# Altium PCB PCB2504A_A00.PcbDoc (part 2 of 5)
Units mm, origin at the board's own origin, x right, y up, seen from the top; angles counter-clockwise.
Board outline 115 x 60 mm, 6 copper layers (Top Layer, Signal Layer 2, Signal Layer 3, Signal Layer 4, Signal Layer 5, Bottom Layer), stack 1.555 mm thick; 403 components, 294 nets, 1344 pads, 774 vias.
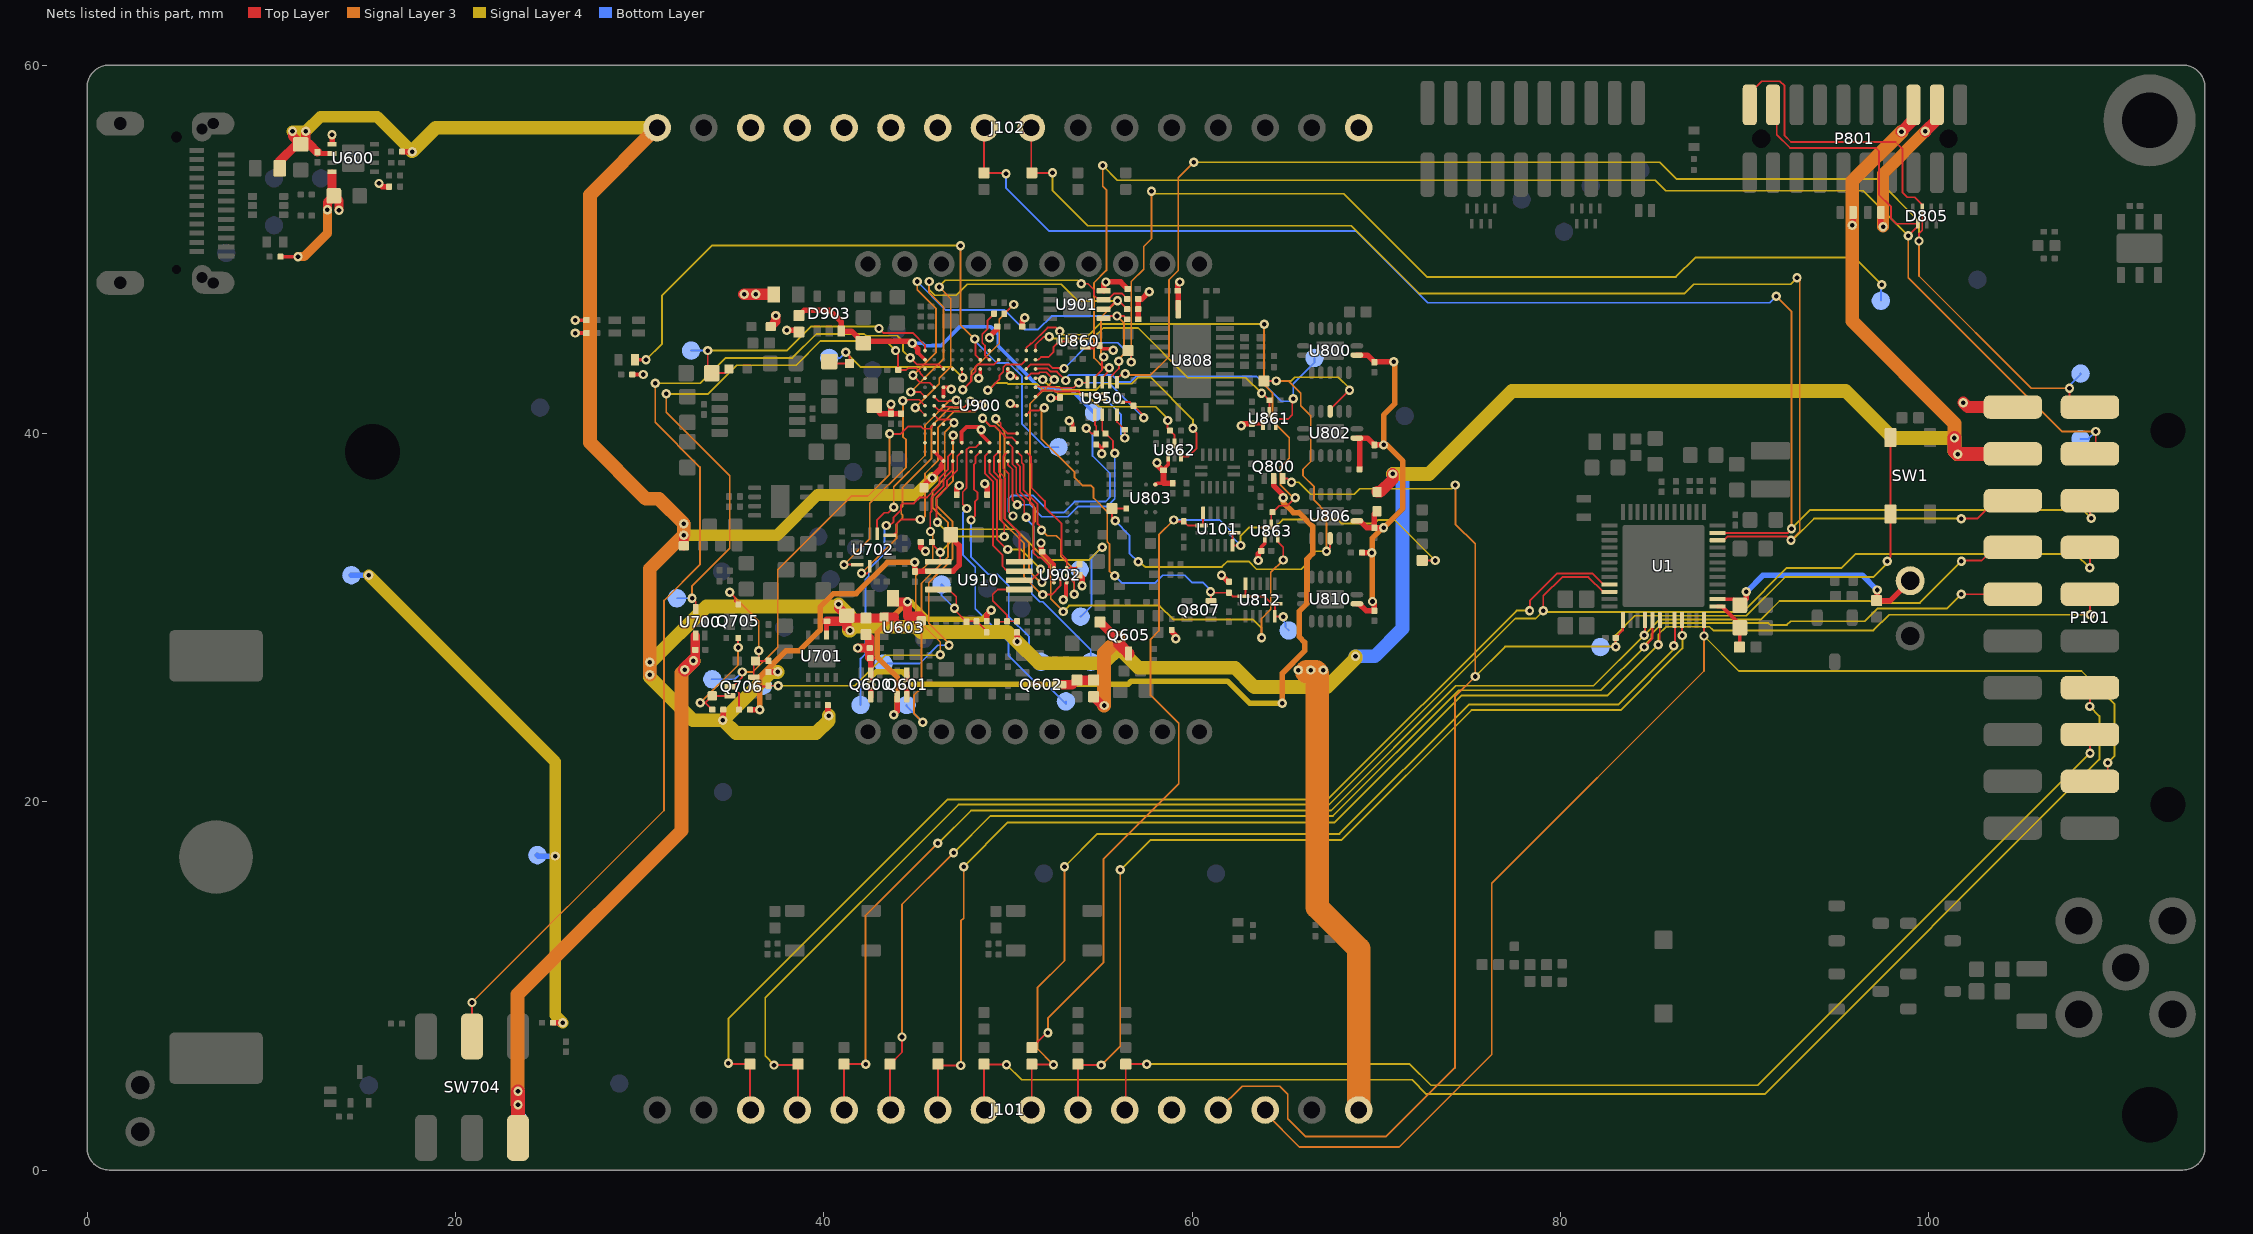
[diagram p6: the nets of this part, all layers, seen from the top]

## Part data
LED900: library part Yellow
LED901: library part Blue

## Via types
v1: diameter 0.508, hole 0.25, Top Layer to Bottom Layer, tented both sides, 774 vias

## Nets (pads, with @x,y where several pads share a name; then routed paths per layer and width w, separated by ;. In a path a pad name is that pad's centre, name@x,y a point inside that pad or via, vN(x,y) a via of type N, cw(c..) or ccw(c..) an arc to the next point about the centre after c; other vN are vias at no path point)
3V3: C607.1 C807.1 C808.1 C860.1 C862.1 C864.1 C866.1 C907.1 C908.1 C909.1 C910.1 C911.1 C914.1 C921.1 C922.1 C924.1 C925.1 C926.1 C927.1 C951.1 D807.1 J101.16 J102.16 L704.1 L900.1 P101.20 P801.3 R601.2 R756.2 R793.2 R838.2 R840.2 R903.1 R906.2 R907.1 R908.1 R909.1 R912.1 R919.1 R920.1 R928.2 R951.1 R952.1 R982.1 TPJ600.1 TPJ950.1 U600.1 U600.4 U803.A2 U808.1 U860.1 U861.1 U862.1 U863.1 U900.C6 U900.C9 U900.G3 U900.H11 U900.J11 U900.K3 U900.L4 U900.L7 U901.8 U902.A1 U902.E3 U910.2 | length 130.7
  Top Layer w0.2: R903.1@10.5,49.6 v1(11.45,49.6) ; U600.1@13.3,55.7 13.3,55.85 ; v1(26.5,45.45) R919.1@27.1,45.45 ; v1(26.5,46.15) R920.1@27.1,46.15 ; R912.1@29.6,43.2 v1(30.2,43.2) ; U900.H11@46.5,42 U900.J11@46.5,42.5 46.825,42.5 v1(46.925,42.4) ; U900.C9@47.5,39.5 47.482,39.518 47.482,40.083 47.749,40.35 48.425,40.35 48.55,40.225 v1@48.55,40.075 ; v1(48.425,43) 48.45,43 48.5,43.05 U900.L7@48.5,43.5 ; v1(48.55,40.2) v1@48.55,40.075 ; U900.C6@49,39.5 48.525,39.975 48.55,40 v1@48.55,40.075 ; U900.L4@50,43.5 50,43.35 50.15,43.2 50.15,43.15 v1(50.125,43.125) 50.375,43.125 U900.K3@50.5,43 ; v1(50.125,41.625) 50.25,41.5 U900.G3@50.5,41.5 ; C914.1@51.875,33.575 51.875,33.525 52.5,32.9 U902.A1@52.5,32.7 ; v1(52.325,41.925) 52.325,41.9 52.4,41.825 52.5,41.925 C911.1@52.825,41.925 ; v1(53,30.975) 53.157,31.132 53.157,31.857 U902.E3@53.2,31.9 ; v1(53.336,40.692) 53.336,40.714 53.325,40.725 53.35,40.725 53.525,40.55 C909.1@53.525,40.225 ; U860.1@54.2,44.65 54.625,44.65 54.75,44.775 C862.1@54.975,44.775 55.157,44.593 55.657,44.593 v1(55.725,44.525) ; R951.1@54.8,39.4 54.9,39.4 55.1,39.2 ; v1(55.1,38.9) 55.1,39.2 ; R952.1@55.3,39.4 55.1,39.2 ; U803.A2@58,37.225 58.032,37.257 58.083,37.257 58.126,37.3 58.475,37.3 ; C860.1@58.45,38 58.45,38.05 58.7,38.3 U862.1@58.7,38.75 ; C864.1@63.25,40.525 63.775,40.525 U861.1@63.85,40.45 ; C866.1@63.75,33.625 63.75,33.825 63.95,34.025 U863.1@63.95,34.35
  Top Layer w0.25: 13.3,54.05 U600.4@13.3,54.2
  Top Layer w0.3: 13.3,55.85 v1(13.3,56.225) ; v1(15.85,53.575) 16.025,53.4 R601.2@16.4,53.4 ; R793.2@25.3,8 v1(25.825,8) ; R756.2@36,25 v1(36.525,25) ; v1(38,45.6) 38.55,45.6 R928.2@38.65,45.5 ; C907.1@42.75,41.4 43.075,41.075 C924.1@43.65,41.075 ; v1(43.65,41.575) C924.1@43.65,41.075 ; C925.1@44.2,41.075 C924.1@43.65,41.075 ; v1(44.95,33) C922.1@44.95,32.5 44.975,32.525 U910.2@46.225,32.525 47.025,32.525 47.35,32.85 47.35,33.925 C921.1@46.825,34.45 ; R982.1@45.275,34.1 45.275,33.8 45.45,33.625 45.5,33.625 v1(45.525,33.6) ; C927.1@47.225,36.675 47.225,37.05 v1(47.35,37.175) ; v1(48.75,37.275) 48.75,37.225 48.875,37.1 C926.1@48.875,36.675 ; v1(49.002,45.202) 48.998,45.202 48.925,45.275 49,45.275 49.425,45.701 C910.1@49.425,45.8 ; C908.1@50.775,45.8 50.775,46.1 50.925,46.25 v1(50.925,46.275) ; v1(51.8,34.05) 51.8,33.65 C914.1@51.875,33.575 ; R906.2@53.899,32.298 54.025,32.172 v1@54.025,31.729 ; v1@54.025,31.725 v1@54.025,31.729 ; v1(54.028,31.727) v1@54.025,31.729 ; U901.8@55.2,47.75 55.2,48.1 v1(55.325,48.225) 56.125,48.225 C951.1@56.5,47.85 ; R908.1@57.075,46.2 R907.1@57.075,46.75 R909.1@57.075,47.3 57.275,47.3 v1(57.675,47.7) ; v1(58.1,38.4) 58.05,38.4 58.025,38.425 58,38.4 58.4,38 C860.1@58.45,38 58.45,37.325 58.475,37.3 C807.1@58.95,37.3 ; R838.2@58.9,29.325 58.9,29.225 59.15,28.975 59.15,28.85 v1(59.125,28.85) ; U808.1@59.25,46.745 59.25,47.725 C808.1@59.225,47.75 59.225,48.125 v1(59.325,48.225) ; v1(61.6,32.3) 61.95,31.95 R840.2@62,31.95 ; v1(62.675,40.425) 62.775,40.525 C864.1@63.25,40.525 ; v1(63.6,33.1) 63.6,33.475 C866.1@63.75,33.625 ; D807.1@97.4,52 97.4,51.35 v1(97.525,51.225)
  Top Layer w0.5: v1(13.05,52.15) 13.05,52.55 C607.1@13.4,52.9 ; 13.3,54.05 13.3,53 C607.1@13.4,52.9 ; v1(13.675,52.125) 13.675,52.625 C607.1@13.4,52.9 ; L704.1@37.125,45.8 37.4,46.075 v1(37.4,46.4)
  Top Layer w0.635: v1(35.675,47.55) v1(36.3,47.55) L900.1@37.285,47.55 ; v1(99.825,56.4) 100.445,57.02 P801.3@100.445,57.841 ; v1(101.875,41.675) 102.12,41.43 P101.20@104.57,41.43
  Signal Layer 3 w0.3: v1(36.525,25) 36.525,26.772 37.964,28.211 38.686,28.211 39.8,29.325 39.8,30.574 40.526,31.3 41.753,31.3 43.453,33 v1(44.95,33) ; v1@48.998,45.202 v1(49.002,45.202)
  Signal Layer 3 w0.5: v1(11.45,49.6) 11.775,49.6 13.05,50.875 v1(13.05,52.15)
  Signal Layer 3 w0.635: v1(97.525,51.225) 97.525,54.1 v1(99.825,56.4)
  Signal Layer 3 w1.27: v1@66.227,27.05 66.725,27.05 66.8,26.975 66.8,14.275 69.05,12.025 J101.16@69.05,3.262
  Signal Layer 4 w0.635: v1(15.3,32.3) 25.425,22.175 v1(25.425,17.05) 25.425,8.4 v1(25.825,8)
  Bottom Layer w0.3: TPJ600.1@14.353,32.302 v1(15.3,32.3) ; TPJ950.1@24.452,17.1 24.502,17.05 v1(25.425,17.05)
  other v1: 65.775,27.15 66.45,27.15 67.125,27.15
3V6_SW: C608.1 L702.1 Q601.1 R639.2 U603.B1 | length 17.3
  Top Layer w0.2: U603.B1@44.55,29.65 44.55,30.075
  Top Layer w0.3: v1@43.8,24.8 v1(43.8,24.725) 44,24.925 Q601.1@44,25.7 ; R639.2@48.85,29.8 48.85,30.15 v1(49.1,30.4) v1@49,30.4
  Top Layer w0.5: L702.1@43.765,31.05 43.965,30.85 v1(44.55,30.85) 44.55,30.075 45.225,30.075 C608.1@45.3,30
  Signal Layer 3 w0.3: v1(43.8,24.725) 44,24.925 44,26.75 42.9,27.85 42.9,29.2 v1(44.55,30.85)
  Signal Layer 4 w0.3: v1(44.55,30.85) 44.75,30.85 45.7,29.9 48.6,29.9 v1(49.1,30.4)
3V6_SW_SENSE: C641.1 R639.1 R640.2 TP923.1 U910.4 | length 6.3
  Top Layer w0.1: U910.4@46.225,31.525 46.795,31.525 47.2,31.12 47.2,30.6 v1(47.1,30.5) ; v1@47.1,30.6 v1(47.1,30.5) ; R639.1@48.85,29.2 48.85,29.25 R640.2@48.3,29.8 47.775,29.8 C641.1@47.75,29.775 47.1,30.425 v1(47.1,30.5)
  Bottom Layer w0.1: TP923.1@46.675,31.525 TP923.1@46.4,31.8 46.4,31.2 v1(47.1,30.5)
5V: C600.1 C609.1 C611.1 C702.1 C703.1 C901.1 D806.1 J102.1 L600.2 L700.1 L800.1 P101.18 P801.5 Q605.3 R600.2 R622.2 R633.2 R680.1 R690.2 R700.2 R714.2 R755.2 U600.2 U603.A2 U603.B2 U701.2 U900.A11 U900.B12 | length 233.2
  Top Layer w0.2: C702.1@40.15,29.775 C702.1@40.175,29.8 ; 43.85,30.025 44.15,29.725 U603.B2@44.15,29.65 44.025,29.65 43.9,29.525 43.9,29.375 44.025,29.25 U603.A2@44.15,29.25 ; U900.B12@46,39 U900.A11@46.5,38.5 46.375,38.375 46.375,38.25
  Top Layer w0.25: C600.1@12.5,55.275 12.575,55.2 U600.2@13.3,55.2 ; U701.2@40.15,29.05 C702.1@40.15,29.775
  Top Layer w0.3: R600.2@17.1,55.3 v1(17.65,55.3) ; v1(34.525,24.425) 34.55,24.425 R714.2@34.55,25 ; R755.2@37,27.05 v1(37.5,27.05) ; R700.2@40.225,25.25 40.225,24.725 v1(40.275,24.675) ; C901.1@45.45,37.05 45.45,37.184 v1@45.902,37.637 ; v1(45.902,37.577) v1@45.902,37.637 ; v1@45.908,37.642 v1@45.902,37.637 ; v1@45.913,37.647 46.375,38.109 46.375,38.25 ; v1(50.5,28.7) R633.2@50.5,29.2 ; v1(95.85,51.3) 95.9,51.35 D806.1@95.9,52
  Top Layer w0.5: L600.2@10.465,54.4 10.465,54.79 11.375,55.7 C611.1@11.6,55.7 ; v1(11.15,56.4) 11.15,56.15 C611.1@11.6,55.7 ; v1(11.875,56.4) 11.875,55.975 C611.1@11.6,55.7 ; C600.1@12.5,55.275 12.075,55.7 C611.1@11.6,55.7 ; L700.1@32.4,33.9 v1(32.4,34.475) ; C702.1@40.175,29.8 40.95,29.8 C703.1@41.25,30.1 ; v1(40.8,30.725) 40.8,30.55 C703.1@41.25,30.1 ; v1(41.425,29.3) 41.25,29.475 C703.1@41.25,30.1 ; 43.85,30.025 C609.1@43.275,30.025 43.225,29.975 R622.2@42.3,29.975 41.375,29.975 C703.1@41.25,30.1 ; R680.1@54.65,25.7 55.125,25.225 v1(55.225,25.225) ; R690.2@55,29.75 55.011,29.75 55.886,28.875 v1(56.025,28.875)
  Top Layer w0.635: v1(56.025,28.875) 56.025,28.575 Q605.3@56.55,28.05 ; L800.1@70.05,36.825 70.225,36.825 70.9,37.5 v1(70.9,37.8) ; v1(98.525,56.375) 99.175,57.025 P801.5@99.175,57.841
  Top Layer w0.75: v1(101.4,39.75) 101.4,39.05 v1(101.575,38.875) 101.59,38.89 P101.18@104.57,38.89
  Signal Layer 3 w0.75: v1(30.55,26.9) v1(30.55,27.575) 30.55,32.65 32.4,34.5 v1(32.4,35.1) 31.05,36.45 30.35,36.45 27.3,39.5 27.3,52.952 J102.1@30.95,56.602 ; v1(55.225,25.225) 55.225,28.075 v1(56.025,28.875) ; v1(98.525,56.375) 95.85,53.7 v1(95.85,51.3) 95.85,46.1 101.4,40.55 v1(101.4,39.75) 101.4,39.05 v1(101.575,38.875)
  Signal Layer 4 w0.635: v1(11.15,56.4) v1(11.875,56.4) 12.675,57.2 15.75,57.2 v1(17.65,55.3) ; v1(32.4,34.475) 37.475,34.475 39.66,36.66 44.986,36.66 v1(45.902,37.577)
  Signal Layer 4 w0.75: v1@17.65,55.318 18.934,56.602 J102.1@30.95,56.602 ; v1(32.4,34.475) v1(32.4,35.1) ; v1(37.5,27.05) 37.15,27.05 v1(34.525,24.425) ; v1(40.275,24.675) 40.275,24.41 39.59,23.725 35.225,23.725 v1(34.525,24.425) ; v1@40.8,30.708 40.692,30.6 33.625,30.6 30.6,27.575 v1(30.55,27.575) v1(30.55,26.9) 30.55,26.775 32.9,24.425 v1(34.525,24.425) ; v1(40.8,30.725) 41.425,30.1 v1(41.425,29.3) ; v1@41.364,29.3 v1(41.425,29.3) ; v1(56.025,28.875) 56.025,28.35 ; v1(68.875,27.9) 68.875,27.775 67.325,26.225 63.375,26.225 62.325,27.275 57.1,27.275 56.025,28.35 ; v1(70.9,37.8) 72.875,37.8 72.975,37.9 77.375,42.3 95.5,42.3 98.05,39.75 v1(101.4,39.75) 101.4,39.05 v1(101.575,38.875) ; v1(41.425,29.3) 41.625,29.5 45,29.5 45.282,29.218 49.982,29.218 v1(50.5,28.7) 51.675,27.525 55.2,27.525 56.025,28.35
  Bottom Layer w0.75: v1(68.875,27.9) 69.925,27.9 71.425,29.4 71.425,37.375 71,37.8 v1(70.9,37.8)
5V_BUF: Q602.3 R680.2 R681.2 | length 2
  Top Layer w0.5: Q602.3@52.8,26.35 53.5,26.35 R681.2@53.75,26.6 R680.2@54.65,26.6
5V_DH_SW: C803.1 C805.1 C809.1 C827.1 L800.2 R807.1 R808.1 U800.14 U802.14 U806.14 U810.14 | length 24.8
  Top Layer w0.3: U810.14@68.95,30.75 69.075,30.75 69.45,30.375 C827.1@69.9,30.375 69.9,30.775 v1(69.8,30.875) ; U806.14@68.95,35.25 69.125,35.25 69.5,34.875 C809.1@69.9,34.875 ; U802.14@68.95,39.75 U802.14@69.1,39.75 ; U800.14@68.95,44.25 69.525,44.25 C803.1@69.9,43.875 69.925,43.9 v1(70.95,43.9) ; R807.1@69.1,38.05 U802.14@69.1,39.75 ; R808.1@69.225,33.525 v1(69.75,33.525) ; L800.2@70.05,35.775 69.9,35.625 C809.1@69.9,34.875 ; v1(70.4,34.875) C809.1@69.9,34.875 ; v1(70.4,39.375) C805.1@69.9,39.375 69.525,39.75 U802.14@69.1,39.75
  Signal Layer 3 w0.3: v1(69.8,30.875) 69.8,30.975 69.775,31 69.775,34.3 70.35,34.875 v1(70.4,34.875) 71.45,35.925 71.45,38.5 70.575,39.375 v1(70.4,39.375) 70.4,41 71,41.6 71,43.85 v1(70.95,43.9)
5V_SENSE: C635.1 R633.1 R634.2 U910.7 | length 4.4
  Top Layer w0.1: C635.1@49.4,29.775 49.925,29.775 R634.2@49.95,29.8 ; R633.1@50.5,29.8 R634.2@49.95,29.8 ; U910.7@50.625,31.525 49.444,31.525 49.182,31.263 49.182,30.918 49.95,30.15 R634.2@49.95,29.8
5V_SW: C610.1 Q600.2 Q600.5 Q601.2 Q601.5 Q800.5 R622.1 R623.2 | length 43.6
  Top Layer w0.3: C610.1@42.525,27.8 42.55,27.775 Q600.5@42.55,27 42.55,26.375 v1(42.55,26.35) Q600.2@42.55,25.7 ; Q601.2@44.5,25.7 v1(44.5,26.375) Q601.5@44.5,27 ; Q800.5@64.425,37.55 64.425,37.175 64.95,36.65 v1(64.95,36.5)
  Top Layer w0.5: v1(41.85,28.35) R623.2@42.5,28.35 ; R622.1@42.3,29.075 42.5,28.875 R623.2@42.5,28.35 ; C610.1@42.525,27.8 42.5,27.825 R623.2@42.5,28.35
  Signal Layer 3 w0.3: v1(64.9,25.35) 64.9,26.975 66.118,28.193 66.118,28.654 65.825,28.947 65.825,30.35 66.243,30.768 66.243,33.168 66.55,33.475 66.55,34.95 65.8,35.7 65.5,35.7 64.95,36.25 v1(64.95,36.5)
  Signal Layer 4 w0.3: v1(42.55,26.35) 42.55,26.751 42.849,27.05 44.275,27.05 44.5,26.825 v1(44.5,26.375) 56.525,26.375 56.7,26.55 61.925,26.55 63.125,25.35 v1(64.9,25.35)
#RESET: R805.2 R809.1 R810.2 U802.4 U806.11 | length 34
  Top Layer w0.1: v1(55.825,35.25) 55.65,35.425 R810.2@55.65,35.925 R809.1@56.425,35.925 ; R805.2@63.9,42.85 v1(64.575,42.85) ; v1(67.3,33.6) 67.5,33.8 U806.11@67.5,34.3 ; U802.4@67.5,41.2 67.5,41.325 68.525,42.35 v1(68.55,42.35)
  Signal Layer 3 w0.1: v1(64.575,42.85) 65.225,42.85 65.9,42.175 65.9,41.506 66.45,40.956 66.45,38.475 66.025,38.05 66.025,37.7 66.625,37.1 66.625,36.375 67.3,35.7 v1(67.3,33.6)
  Signal Layer 4 w0.1: v1(57.075,33.025) 57.175,33.025 57.432,32.768 57.438,32.768 57.456,32.75 61.625,32.75 61.925,33.05 63.075,33.05 63.5,32.625 65.925,32.625 66.357,33.057 66.357,33.257 66.7,33.6 v1(67.3,33.6) ; v1(64.575,42.85) 65.381,42.85 65.581,43.05 67.95,43.05 68.55,42.45 v1(68.55,42.35)
  Bottom Layer w0.1: v1(55.825,35.25) 56.6,34.475 56.6,33.5 v1(57.075,33.025)
ADC0: C130.1 R129.2 U1.25 | length 2.9
  Top Layer w0.2: U1.25@88.535,30.6 88.775,30.6 89.75,29.625 C130.1@89.75,29.45 89.75,28.425 R129.2@89.725,28.4
ADC1: J101.14 P101.3 U1.24 | length 72.6
  Top Layer w0.1: v1(87.8,29) U1.24@87.8,29.865 ; P101.3@108.76,21.11 109.385,21.11 109.725,21.45 v1(109.725,22.125)
  Signal Layer 3 w0.1: J101.14@63.97,3.262 63.97,3.105 65.825,1.25 71.25,1.25 76.275,6.275 76.275,15.575 87.8,27.1 v1(87.8,29)
  Signal Layer 4 w0.1: v1(87.8,29) 89.7,27.1 108.3,27.1 110.1,25.3 110.1,22.5 v1(109.725,22.125)
ADC_VREF: C117.1 R116.1 TPH101.1 U1.26 | length 12.9
  Top Layer w0.2: U1.26@88.535,31 89.425,31 C117.1@89.75,30.675
  Top Layer w0.3: C117.1@89.75,30.675 90.1,31.025 v1(90.1,31.4) ; v1(97.2,31.5) 97.2,30.95 R116.1@97.175,30.925 97.925,30.925 TPH101.1@99,32
  Bottom Layer w0.3: v1(90.1,31.4) 91,32.3 96.4,32.3 v1(97.2,31.5)
ADC_VREF_ENABLE: R112.1 R118.2 R306.2 U101.5 U101.6 U101.12 U101.13 | length 54.5
  Top Layer w0.1: R306.2@51.3,6.65 52.1,7.45 v1(52.175,7.45) ; v1(59,35.3) 59.075,35.225 R112.1@59.55,35.225 59.775,35 U101.13@60.515,35 60.6,35.085 U101.12@60.6,35.685 U101.12@60.6,35.95 ; U101.6@62.285,34.6 62.2,34.515 U101.5@62.2,33.915 v1(62.64,33.915) ; R118.2@72.5,33.1 v1(73.2,33.1)
  Signal Layer 3 w0.1: v1(52.175,7.45) 52.175,8.25 55.2,11.275 55.2,16.9 59.275,20.975 59.275,24.25 57.75,25.775 57.75,28.825 58.2,29.275 58.2,34.5 v1(59,35.3)
  Signal Layer 4 w0.1: v1(62.64,33.915) 62.64,34.44 63.1,34.9 64.5,34.9 64.918,35.318 67.918,35.318 68.136,35.1 69.9,35.1 70.1,35.3 71,35.3 v1(73.2,33.1)
  Bottom Layer w0.1: v1(59,35.3) 61.5,35.3 62.07,34.73 62.07,34.485 v1(62.64,33.915)
AEM_5V_#ENABLE: U900.L10
AEM_BYPASS_#EN: C709.1 Q705.2 Q706.6 R714.1 | length 6.6
  Top Layer w0.1: v1(33.3,25.375) 33.575,25.375 ; R714.1@33.95,25 33.575,25.375 ; Q706.6@34.9,25.75 C709.1@33.95,25.75 33.575,25.375 ; v1(35.35,28.375) Q705.2@35.35,28.888
  Signal Layer 3 w0.1: v1(33.3,25.375) 35.35,27.425 v1(35.35,28.375)
AEM_BYPASS_ENABLE: Q706.2 R754.2 TP720.1 U900.F12 | length 27.4
  Top Layer w0.1: Q706.2@36.2,26.25 36.95,26.25 R754.2@37,26.3 v1(37.525,26.3) ; U900.F12@46,41 46.25,40.75 46.9,40.75 v1(47.075,40.575)
  Signal Layer 3 w0.1: v1@46.325,27.95 v1(46.325,27.975) 46.325,28.675 45.3,29.7 45.3,31.85 46.75,33.3 46.75,35.15 46.568,35.332 46.568,35.338 46.338,35.568 46.332,35.568 45.9,36 45.9,36.9 46.575,37.575 46.575,40.075 v1(47.075,40.575)
  Signal Layer 4 w0.1: v1(37.525,26.3) 41.675,26.3 43.332,27.957 46.307,27.957 v1(46.325,27.975)
  Bottom Layer w0.1: TP720.1@36.7,26.3 v1(37.525,26.3)
AEM_CALIBRATE0: U702.13 U900.G11 | length 14.9
  Top Layer w0.1: v1(42.05,32.4) 41.95,32.4 42.35,32.4 42.5,32.55 U702.13@42.5,32.79 ; U900.G11@46.5,41.5 46.55,41.45 46.999,41.45 47.04,41.409 47.609,41.409 v1(47.952,41.752) 47.975,41.775 v1@48,41.775
  Signal Layer 3 w0.1: v1(42.05,32.4) 43.425,33.775 43.957,34.307 43.957,35.088 44.275,35.406 44.275,35.55 44.275,35.569 44.207,35.637 44.207,35.963 44.275,36.031 44.275,37.05 45.85,38.625 45.85,40.4 46.85,41.4 47.6,41.4 v1(47.952,41.752)
AEM_CALIBRATE1: U702.5 U900.G12 | length 13.4
  Top Layer w0.1: U702.5@43.585,34.475 43.775,34.475 43.957,34.657 43.957,35.088 44.194,35.325 v1(45.25,35.325) ; U900.G12@46,41.5 46.25,41.25 46.604,41.25 46.652,41.202 48.227,41.202 v1(48.575,41.55)
  Signal Layer 3 w0.1: v1(45.25,35.325) 45.35,35.325 45.5,35.475 45.5,37.825 46.2,38.525 46.2,40.3 47.093,41.193 48.218,41.193 v1(48.575,41.55)
AEM_CALIBRATE2: U702.6 U900.H12 | length 10.7
  Top Layer w0.1: U702.6@42.9,34.56 42.9,35.306 43.287,35.693 43.493,35.693 v1(43.8,36) ; U900.H12@46,42 46.25,41.75 47.15,41.75 v1(47.202,41.802)
  Signal Layer 3 w0.1: v1(43.8,36) 43.8,37.1 45.5,38.8 45.5,40.45 46.852,41.802 v1(47.202,41.802)
AEM_CALIBRATE3: U702.12 U900.G13 | length 12.6
  Top Layer w0.1: v1(41.1,32.875) U702.12@41.815,32.875 ; v1(44.3,41.775) 44.3,41.657 44.332,41.625 44.532,41.825 45.175,41.825 U900.G13@45.5,41.5
  Signal Layer 3 w0.1: v1(41.1,32.875) 42.5,34.275 42.5,36.2 44.475,38.175 44.475,39.656 44.3,39.831 v1(44.3,41.775)
AEM_CURRENT_HIGH_GAIN: C720.1 R764.2 TP706.1 U900.N13 | length 16.3
  Top Layer w0.1: v1(33.7,44.5) 33.7,43.5 R764.2@33.925,43.275 34.625,43.275 C720.1@34.85,43.5 ; v1(43,45.7) 43.25,45.45 44.85,45.45 45.5,44.8 U900.N13@45.5,44.5
  Signal Layer 4 w0.1: v1(33.7,44.5) 38,44.5 39.3,45.8 42.9,45.8 v1(43,45.7)
  Bottom Layer w0.1: TP706.1@32.8,44.5 v1(33.7,44.5)
AEM_CURRENT_LOW_GAIN: C724.1 R768.2 TP707.1 U900.L9 | length 10.3
  Top Layer w0.1: R768.2@40.3,43.9 40.4,43.8 C724.1@41.4,43.8 41.4,44.2 v1(41.2,44.4) ; U900.L9@47.5,43.5 47.5,43.2 47.575,43.125 v1@47.552,43.102 ; v1(47.55,43.025) v1@47.55,43.1 ; v1@47.55,43.1 47.525,43.1 47.527,43.102 v1@47.552,43.102 ; v1@47.55,43.1 v1@47.552,43.102
  Signal Layer 4 w0.1: v1(41.2,44.4) 42,43.6 46.975,43.6 v1(47.55,43.025)
  Bottom Layer w0.1: TP707.1@40.3,44.1 40.9,44.1 v1(41.2,44.4)
AEM_SENSE_#EN: C747.1 Q705.5 Q706.3 R755.1 | length 6.9
  Top Layer w0.1: v1(34.902,31.377) 35.169,31.109 35.169,30.894 Q705.5@35.35,30.713 ; Q706.3@36.2,26.75 36.2,27.55 C747.1@36.3,27.65 ; v1(36.475,28.2) 36.475,27.825 C747.1@36.3,27.65 ; R755.1@37,27.65 C747.1@36.3,27.65
  Signal Layer 3 w0.1: v1(34.902,31.377) 36.475,29.803 v1(36.475,28.2)
AEM_SENSE_ENABLE: Q706.5 R756.1 TP721.1 U900.E12 | length 24.3
  Top Layer w0.1: Q706.5@34.9,26.25 Q706.5@35.05,26.25 ; R756.1@35.4,25 35.4,25.9 Q706.5@35.05,26.25 ; v1(35.567,27.046) 35.567,26.767 Q706.5@35.05,26.25 ; v1(43.575,39.975) 44.179,39.975 44.586,40.382 45.264,40.382 45.396,40.25 45.75,40.25 U900.E12@46,40.5
  Signal Layer 3 w0.1: v1(35.567,27.046) 36.146,27.046 37.5,28.4 37.5,32.6 41.5,36.6 42.4,36.6 43.575,37.775 v1(43.575,39.975)
  Bottom Layer w0.1: TP721.1@33.9,26.65 TP721.1@33.95,26.65 35.171,26.65 v1(35.567,27.046)
AEM_SENSE_SELECT: U900.L13
AEM_SWITCH_POS: SW704.2 U900.L11 | length 59.4
  Top Layer w0.1: SW704.2@20.9,7.25 v1(20.9,9.1) ; v1(44.7,44.1) 45.05,43.75 46.25,43.75 U900.L11@46.5,43.5
  Signal Layer 3 w0.1: v1(20.9,9.1) 31.325,19.525 31.325,30.925 33.275,32.875 33.275,38.175 30.85,40.6 v1(30.85,42.725)
  Signal Layer 4 w0.1: v1(30.85,42.725) 33.3,42.725 34.675,44.1 38.3,44.1 39.6,45.4 42.2,45.4 42.3,45.3 43.5,45.3 44,45.3 44.3,45 44.3,44.5 v1(44.7,44.1)
AEM_VMCU: C708.1 SW704.4 TP709.1 U700.1 | length 34.2
  Top Layer w0.5: v1(32.925,27.65) 33.025,27.75 C708.1@33.025,28.25 U700.1@33.025,29
  Top Layer w0.75: SW704.4@23.4,1.75 v1(23.4,3.55) v1(23.4,4.275) ; v1(32.45,27.175) v1(32.925,27.65)
  Signal Layer 3 w0.75: v1(23.4,3.55) 23.375,3.575 23.375,9.525 32.275,18.425 32.275,27 v1(32.925,27.65)
  Bottom Layer w0.635: v1(23.4,4.275) v1(23.4,3.55) 23.425,3.525 TP709.1@23.425,2.725
AEM_VMCU_ENABLE: R763.2 TP715.1 U700.4 U900.K13 | length 31.6
  Top Layer w0.1: v1(32.85,31.05) 33.05,30.85 U700.4@33.05,30.475 ; v1(43.9,44.5) 44.025,44.375 44.025,43.475 R763.2@44.05,43.45 44.485,43.45 44.578,43.543 45.013,43.543 45.243,43.313 45.243,43.257 U900.K13@45.5,43
  Signal Layer 3 w0.1: v1(31.45,42.15) 31.45,41.15 34.9,37.7 34.9,33.775 32.85,31.725 v1(32.85,31.05)
  Signal Layer 4 w0.1: v1(31.45,42.15) 33.725,42.15 35.275,43.7 38.5,43.7 39.825,45.025 43.375,45.025 v1(43.9,44.5)
  Bottom Layer w0.1: TP715.1@32.025,31.05 v1(32.85,31.05)
BC_ADC_SPI_CIPO: U900.B6 U910.9 | length 9.2
  Top Layer w0.1: U900.B6@49,39 48.75,38.75 48.75,37.831 49.2,37.381 49.2,33.9 ; 49.2,35.4 49.2,33.9 ; U910.9@50.625,32.525 49.975,32.525 49.7,32.8 49.7,33.4 49.2,33.9
BC_ADC_SPI_COPI: U900.A6 U910.8 | length 9
  Top Layer w0.1: U900.A6@49,38.5 49,37.863 49.4,37.463 49.4,35 49.4,34.7 49.4,34.244 49.944,33.7 v1(50,33.7) v1@50,33.65 ; U910.8@50.625,32.025 51.275,32.025 51.775,32.525 v1(51.775,32.625)
  Signal Layer 4 w0.1: v1(50,33.7) 50.7,33.7 v1(51.775,32.625)
BC_ADC_SPI_CS: R982.2 U900.B5 U910.1 | length 10.7
  Top Layer w0.1: R982.2@45.875,34.1 45.875,34 v1(46.325,33.55) 46.325,33.125 U910.1@46.225,33.025 ; U900.B5@49.5,39 49.25,38.75 49.25,37.896 49.65,37.496 49.65,35.25 ; 49.65,35.811 49.65,35.25 ; v1@49.8,34.275 v1(49.8,34.4) 49.8,35.1 49.65,35.25
  Signal Layer 4 w0.1: v1(46.325,33.55) 47.175,34.4 v1(49.8,34.4)
BC_ADC_SPI_SCLK: U900.A5 U910.10 | length 5.9
  Top Layer w0.1: U900.A5@49.5,38.5 49.5,37.929 49.85,37.579 49.85,35.375 50.625,34.6 U910.10@50.625,33.025
BC_ADC_VREF: C919.1 D903.3 R928.1 TPJ905.1 U900.M13 | length 21.3
  Top Layer w0.2: 45.1,44.4 U900.M13@45.5,44
  Top Layer w0.3: R928.1@38.65,46.4 38.95,46.7 40.325,46.7 40.95,46.075 D903.3@40.95,45.55 41.5,45.55 C919.1@42.15,44.9 42.25,45 44.4,45 44.7,45 v1(44.8,44.9) 45.1,44.6 45.1,44.4
  Bottom Layer w0.2: v1(44.8,44.9) 45.374,44.9 45.517,44.757 45.883,44.757 45.901,44.775 46.375,44.775 47.4,45.8 49.05,45.8 49.475,45.375 49.475,44.75 51.2,43.025 51.2,42.999 51.774,42.425 53.379,42.425 TPJ905.1@54.678,41.126
BC_BUTTON_ENABLE: R981.1 U900.H1 U950.6 U950.12 | length 8.2
  Top Layer w0.1: U900.H1@51.5,42 51.832,42.332 52.474,42.332 52.526,42.28 53.845,42.28 54.025,42.1 U950.6@54.24,42.1 55.075,42.1 v1(55.175,42) ; U950.12@55.925,41.015 55.925,40.625 R981.1@56.35,40.2 v1(56.35,39.75)
  Bottom Layer w0.1: v1@55.1,42.075 v1(55.175,42) 56.138,41.037 56.138,39.962 v1(56.35,39.75)
BC_DAC_OUT: U900.N6
BC_DBG_#RESET: LED903.1 TPJ956.1 U900.M7 | length 37
  Top Layer w0.1: v1(48.2,45.125) 48.25,45.075 48.25,44.25 U900.M7@48.5,44
  Top Layer w0.2: LED903.1@29.75,44 v1(30.35,44)
  Signal Layer 3 w0.1: v1(47.425,50.2) 47.425,45.9 v1(48.2,45.125)
  Signal Layer 4 w0.1: v1(30.35,44) 31.225,44.875 31.225,47.5 33.925,50.2 v1(47.425,50.2)
  Bottom Layer w0.1: v1(48.2,45.125) 48.2,45.025 49.4,43.825 50.046,43.825 50.775,43.096 50.775,40.5 52.024,39.251 TPJ956.1@52.753,39.251
BC_DBG_TCK_SWCLK: TPJ954.1 U900.C10 | length 18.5
  Top Layer w0.1: U900.C10@47,39.5 47,39.775 46.95,39.825 46.95,39.85 47,39.9 v1(47.025,39.9) ; v1@47.125,39.852 v1@47.125,39.9
  Signal Layer 3 w0.1: 46.25,32.45 45.7,31.9 ; v1(46.8,28.5) 46.8,28.6 45.7,29.7 45.7,31.9 ; v1(47.025,39.9) 47.025,37.425 46.132,36.532 46.132,36.068 47,35.2 47,33.2 45.7,31.9
  Bottom Layer w0.1: TPJ954.1@43.253,27.501 45.201,27.501 46.2,28.5 v1(46.8,28.5) ; v1@46.957,39.832 v1(47.025,39.9)
BC_DBG_TDO_SWO: TPJ955.1 U900.A10 | length 17
  Top Layer w0.1: v1@45.85,34.725 v1(45.8,34.675) 45.782,34.693 45.782,35.699 45.85,35.767 45.85,36.484 46.495,37.129 46.495,37.522 47,38.027 U900.A10@47,38.5
  Signal Layer 3 w0.1: v1(45.375,24.325) 44.9,24.8 44.9,25.775 45.318,26.193 45.318,29.282 45,29.6 45,32.264 45.918,33.182 45.918,34.557 v1(45.8,34.675)
  Bottom Layer w0.1: TPJ955.1@44.503,25.251 44.503,25.197 v1(45.375,24.325)
BC_DBG_TMS_SWDIO: TPJ953.1 U900.B10 | length 16.8
  Top Layer w0.1: v1(43.4,35) 43.587,35 43.793,35.207 43.793,35.438 44.193,35.837 44.193,36.093 44.3,36.2 44.9,36.2 45.225,36.525 45.608,36.525 46.295,37.212 46.295,37.605 46.75,38.06 46.75,38.75 U900.B10@47,39
  Bottom Layer w0.1: TPJ953.1@42.001,25.251 42.001,27.776 42.275,28.05 42.275,32.069 42.443,32.237 42.443,32.618 43.3,33.475 43.3,35.15 43.4,35.05 v1(43.4,35)
BC_DISP_COM: U900.E11
BC_DISP_PWR_ENABLE: U900.D12
BC_DISP_SPI_COPI: U900.B8
BC_DISP_SPI_CS: U900.C12
BC_DISP_SPI_SCLK: U900.C13
BC_I2C_EXP_ENABLE: R950.1 U900.J1 U950.5 U950.13 | length 9.1
  Top Layer w0.1: U900.J1@51.5,42.5 51.5,42.532 52.556,42.532 52.608,42.48 53.58,42.48 v1(53.85,42.75) 54.29,42.75 U950.5@54.325,42.785 ; U950.13@56.01,41.7 56.625,41.7 R950.1@56.825,41.5 57.375,40.95 v1(57.375,40.85)
  Bottom Layer w0.1: v1(53.85,42.75) 55.475,42.75 v1(57.375,40.85)
BC_I2C_EXP_SCL: D805.5 P101.17 P801.17 TPJ651.1 U950.3 | length 90.4
  Top Layer w0.1: U950.3@55.125,42.785 55.125,43.025 55.275,43.175 ; 55.275,43.175 55.375,43.275 55.4,43.3 55.4,43.475 v1(55.5,43.575) ; P801.17@91.555,57.841 91.75,57.647 91.75,56.225 92.475,55.5 97.15,55.5 97.3,55.35 97.3,52.975 97.95,52.325 97.95,51.675 98.24,51.385 D805.5@99.4,51.385 99.4,51.25 v1(98.892,50.742) ; P101.17@108.76,38.89 108.76,39.135 109.075,39.45 109.075,40 109.025,40.05 109.077,40.102 v1(109.08,40.102)
  Signal Layer 3 w0.1: v1(55.15,54.55) 55.15,53.431 55.35,53.231 55.35,48.85 54.675,48.175 54.675,44.1 55.2,43.575 v1(55.5,43.575) ; v1(98.892,50.742) 98.892,48.458 107.248,40.102 v1(109.08,40.102)
  Signal Layer 4 w0.1: v1(55.15,54.55) 55.95,53.75 85.15,53.75 85.725,53.175 96.459,53.175 v1(98.892,50.742)
  Bottom Layer w0.1: TPJ651.1@108.25,39.7 108.678,39.7 v1(109.08,40.102)
BC_I2C_EXP_SDA: D805.3 P101.19 P801.19 TPJ650.1 U950.1 | length 90.1
  Top Layer w0.1: U950.1@55.925,42.785 55.925,42.975 56.2,43.25 v1(56.375,43.25) ; P801.19@90.285,57.841 90.285,58.485 90.925,59.125 91.925,59.125 92.175,58.875 92.175,56.175 92.525,55.825 98.2,55.825 98.575,55.45 98.575,53.1 98.85,52.825 99.25,52.825 99.65,52.425 D805.3@99.65,52.215 99.65,51.025 99.475,50.85 v1(99.475,50.45) ; v1(107.65,42.45) 107.65,41.8 108.02,41.43 P101.19@108.76,41.43
  Signal Layer 3 w0.1: v1(56.375,43.25) 56.45,43.175 57.75,43.175 58.75,44.175 58.75,48.348 59.25,48.848 59.25,53.875 v1(60.1,54.725) ; v1(99.475,50.45) 99.475,48.55 105.575,42.45 v1(107.65,42.45)
  Signal Layer 4 w0.1: v1(60.1,54.725) 85.4,54.725 86.3,53.825 97.175,53.825 99.475,51.525 v1(99.475,50.45)
  Bottom Layer w0.1: v1(107.65,42.45) 107.65,42.625 108.25,43.225 TPJ650.1@108.25,43.248
BC_SPI_CIPO: U900.B3 U902.C3 | length 10.5
  Top Layer w0.1: U900.B3@50.5,39 50.75,38.75 50.75,38.396 50.85,38.296 50.85,36.921 51.61,36.16 51.61,35.09 51.825,34.875 v1(51.825,34.75) ; U902.C3@53.2,32.3 53.6,31.9 v1(53.6,31.275)
  Signal Layer 3 w0.1: v1(51.825,34.75) 52.132,34.443 52.638,34.443 52.868,34.213 52.868,33.332 53.6,32.6 v1(53.6,31.275)
BC_SPI_COPI: U900.C3 U902.D2 | length 15
  Top Layer w0.1: v1(48.625,40.825) 49.043,40.407 49.284,40.407 49.916,39.775 50.225,39.775 U900.C3@50.5,39.5 ; v1(51.9,31.25) 52.375,31.25 52.85,31.725 U902.D2@52.85,32.1
  Signal Layer 3 w0.1: v1(48.625,40.825) 49.05,40.4 49.282,40.4 49.565,40.117 49.565,35.335 50.875,34.025 50.875,32.225 51.85,31.25 v1(51.9,31.25)
BC_SPI_CS: R906.1 U900.B2 U902.A3 | length 8
  Top Layer w0.1: U900.B2@51,39 51.25,38.75 51.25,38.396 51.3,38.346 51.3,37.037 52.01,36.326 52.01,35.995 52.92,35.086 52.92,33.424 53.2,33.144 U902.A3@53.2,32.7 53.701,32.7 R906.1@53.899,32.898
BC_SPI_SCLK: U900.A3 U902.E1 | length 7.5
  Top Layer w0.1: U900.A3@50.5,38.5 50.5,38.364 50.65,38.214 50.65,36.838 51.4,36.088 51.4,33.5 51.635,33.265 51.781,33.265 52.238,32.809 52.238,32.162 U902.E1@52.5,31.9
BC_TRACECLK: TPJ957.1 U900.B7 | length 13.6
  Top Layer w0.1: v1(48,35.3) 48.207,35.507 48.207,36.301 48.343,36.437 48.343,36.794 48.157,36.979 48.157,38.304 48.25,38.396 48.25,38.75 U900.B7@48.5,39
  Bottom Layer w0.1: v1(48,35.3) 48,33.275 48.925,32.35 49.425,32.35 50.05,31.725 50.05,30.05 51.15,28.95 51.15,28.248 TPJ957.1@51.799,27.599
BC_TRACED0: TPJ958.1 U900.C7 | length 17.7
  Top Layer w0.1: v1(47.775,35.925) 47.55,36.15 47.55,36.819 47.75,37.019 47.75,38.55 47.75,39.104 47.896,39.25 48.25,39.25 U900.C7@48.5,39.5
  Bottom Layer w0.1: v1(47.775,35.925) 47.568,35.718 47.568,33.382 48.225,32.725 48.225,30.475 50.025,28.675 50.025,27.95 51.575,26.4 52.059,26.4 53.15,25.309 TPJ958.1@53.15,25.45
BC_TRACED1: TPJ959.1 U900.C4 | length 14
  Top Layer w0.1: U900.C4@50,39.5 50.25,39.25 50.25,38.331 50.45,38.131 50.45,36.755 50.893,36.312 50.893,35.532 v1@50.975,35.45 ; v1@51,35.425 v1@50.975,35.45 ; v1(51,35.45) v1@50.975,35.45
  Bottom Layer w0.1: v1(51,35.45) 51,35.375 51.407,34.968 51.407,33.718 51.3,33.611 51.3,31.294 51.737,30.857 51.893,30.857 54.499,28.251 TPJ959.1@54.499,27.599
BC_TRACED2: TPJ960.1 U900.D3 | length 13.9
  Top Layer w0.1: v1(49.35,40.8) 49.61,40.54 49.61,40.364 49.974,40 U900.D3@50.5,40
  Signal Layer 3 w0.1: v1(49.35,40.8) 49.35,40.615 49.765,40.2 49.765,40.16 49.825,40.1 49.825,35.375 51.137,34.062 51.137,32.538 51.75,31.925 v1(51.85,31.925)
  Bottom Layer w0.1: v1(51.85,31.925) 52.523,32.598 TPJ960.1@53.899,32.598
BC_TRACED3: TPJ961.1 U900.B9 | length 18.8
  Top Layer w0.1: v1(46.175,35.175) 46.132,35.218 46.132,36.484 46.695,37.047 46.695,37.44 47.25,37.994 47.25,38.75 U900.B9@47.5,39
  Signal Layer 4 w0.1: v1(46.175,35.175) 46.55,34.8 50.425,34.8 52.1,33.125 54.4,33.125 55.1,33.825 v1(55.125,33.825)
  Bottom Layer w0.1: TPJ961.1@53.95,30.05 54.549,30.649 54.549,33.249 54.7,33.4 v1(55.125,33.825)
BC_UIF_BUTTON0: R951.2 U900.B4 U950.9 | length 17.2
  Top Layer w0.1: U900.B4@50,39 49.75,38.75 49.75,38.1 50.05,37.8 50.05,35.74 v1(50.275,35.515) ; v1(54.25,40.275) 54.525,40 R951.2@54.8,40 54.8,40.4 54.725,40.475 U950.9@54.725,41.015
  Bottom Layer w0.1: v1(50.275,35.515) 50.025,35.765 50.025,36.45 50.2,36.625 51.375,36.625 52.3,35.7 53.025,35.7 53.625,36.3 55.3,36.3 55.55,36.55 55.55,37.825 54.6,38.775 54.6,39.925 v1(54.25,40.275) v1@54.194,40.275
BC_UIF_BUTTON1: R952.2 U900.A4 U950.10 | length 13.4
  Top Layer w0.1: U900.A4@50,38.5 50,38.298 50.25,38.048 50.25,36.375 v1(50.5,36.125) ; U950.10@55.125,41.015 55.125,40.175 R952.2@55.3,40 55.71,39.59 55.71,39.015 v1(55.8,38.925)
  Bottom Layer w0.1: v1(50.5,36.125) 51.2,36.125 51.85,35.475 53.25,35.475 53.8,36.025 55.375,36.025 55.8,36.45 v1(55.8,38.925)
BC_VCOM_CTS: U863.3 U900.K2 | length 34
  Top Layer w0.1: U900.K2@51,43 51.25,43.25 51.669,43.25 51.737,43.318 52.086,43.318 52.525,42.879 v1(52.525,42.925) ; v1@52.5,42.825 52.55,42.775 v1@52.575,42.8 ; U863.3@64.65,34.35 64.65,34.125 64.95,33.825 v1(64.95,33.125)
  Signal Layer 3 w0.1: v1(52.525,42.925) 51.2,41.6 51.2,36.2 51.475,35.925 51.475,35.225 51.375,35.125 51.375,33.825 52.325,32.875 52.325,31.025 52.975,30.375 v1@52.975,30.3 ; v1@52.975,30.275 v1@52.975,30.3 ; v1@53.001,30.326 v1@52.975,30.3 ; v1(63.775,28.9) 63.775,29.95 64.275,30.45 64.275,32.45 v1(64.95,33.125)
  Signal Layer 4 w0.1: v1(53.003,30.326) 53.326,30.65 58.225,30.65 58.975,29.9 63.306,29.9 63.775,29.431 v1(63.775,28.9)
BC_VCOM_CTS_DIR: R853.2 U863.5 U900.N2 | length 27
  Top Layer w0.1: U900.N2@51,44.5 51,44.642 51.233,44.875 51.283,44.875 52.158,45.75 52.625,45.75 v1(52.825,45.55) ; U863.5@64.3,35.05 64.3,35.65 R853.2@64.375,35.725 64.725,36.075 65.175,36.075 v1(65.6,36.5)
  Signal Layer 3 w0.1: v1(63.925,45.925) 63.9,45.9 63.9,42.667 64.375,42.192 64.375,40.669 65.275,39.769 65.275,38.656 64.982,38.363 64.982,38.357 64.8,38.175 64.8,37.206 v1@65.6,36.406 ; v1(65.6,36.5) v1@65.6,36.406 ; v1@65.65,36.356 v1@65.6,36.406
  Signal Layer 4 w0.1: v1(52.825,45.55) 53.018,45.357 54.407,45.357 55,45.95 v1@63.925,45.95
BC_VCOM_ENABLE: Q807.3 R840.1 TP930.1 U812.5 U812.6 U812.12 U812.13 U900.F2 | length 25.5
  Top Layer w0.1: U900.F2@51,41 51.25,41.25 51.7,41.25 51.85,41.4 v1(51.975,41.4) ; v1(61,31.4) v1@61.025,31.375 ; Q807.3@61.15,30.9 Q807.3@61.025,30.9 v1@61.025,31.375 ; U812.12@62.9,31.835 62.9,31.235 U812.13@62.815,31.15 ; U812.6@64.585,30.75 U812.6@64.5,30.75 ; v1(64.95,30.05) 64.935,30.065 U812.5@64.5,30.065 U812.6@64.5,30.75 ; v1@61.025,31.375 61.05,31.35 R840.1@62,31.35 62.2,31.15 U812.13@62.815,31.15 ; U812.13@62.815,31.15 63.925,31.15 64.325,30.75 U812.6@64.5,30.75
  Signal Layer 3 w0.1: v1(51.975,41.4) 51.832,41.257 51.832,39.693 53.625,37.9 53.625,37.6 54.05,37.175 54.5,37.175 54.657,37.018 54.657,36.493 55.4,35.75 55.4,34.106 55.518,33.988 55.518,32.507 55.775,32.25 55.8,32.25 55.803,32.253 v1(55.803,32.277)
  Bottom Layer w0.1: v1(55.803,32.277) 56.204,31.875 57.975,31.875 58.4,32.3 59.6,32.3 60,31.9 60.6,31.9 61,31.5 v1(61,31.4) ; v1(64.95,30.05) 64.95,29.825 65.075,29.7 65.075,29.475 TP930.1@65.25,29.3
BC_VCOM_RTS: U862.3 U900.K1 | length 12.7
  Top Layer w0.1: U900.K1@51.5,43 51.825,43 v1(51.9,42.925) ; U862.3@59.4,38.75 59.8,38.75 60.25,39.2 60.25,40 60.05,40.2 v1(60.05,40.275)
  Signal Layer 4 w0.1: v1(51.9,42.925) 52.3,42.525 52.799,42.525 52.974,42.35 54.775,42.35 55.125,42.7 56.725,42.7 57.068,43.043 57.757,43.043 60.05,40.75 v1(60.05,40.275)
BC_VCOM_RTS_DIR: R852.2 U862.5 U900.M2 | length 15.3
  Top Layer w0.1: v1(48.9,42.35) 48.956,42.35 49.54,42.935 49.54,43.14 49.75,43.35 49.75,43.604 49.896,43.75 50.75,43.75 U900.M2@51,44 ; v1(58.675,40.7) 58.675,40.275 R852.2@58.8,40.15 59.05,39.9 U862.5@59.05,39.45
  Signal Layer 4 w0.1: v1(48.9,42.35) 48.956,42.35 49.349,42.743 49.943,42.743 50.011,42.675 51.594,42.675 51.944,42.325 52.55,42.325 52.725,42.15 54.225,42.15 54.925,41.45 58.031,41.45 58.675,40.806 v1(58.675,40.7)
BC_VCOM_RXD: R882.2 TPJ606.1 U900.L2 | length 61
  Top Layer w0.1: U900.L2@51,43.5 51.25,43.75 52.219,43.75 52.412,43.557 53.018,43.557 v1(53.05,43.525) ; R882.2@56.525,44.5 56.7,44.325 v1(56.7,43.875)
  Signal Layer 3 w0.1: v1(56.7,43.875) 56.7,48.25 57.375,48.925 57.375,50.15 57.8,50.575 v1(57.8,53.15)
  Signal Layer 4 w0.1: v1(57.8,53.15) 57.932,53.018 68.232,53.018 72.75,48.5 86.275,48.5 87.325,49.55 95.982,49.55 v1(97.455,48.077)
  Bottom Layer w0.1: v1(53.05,43.525) 54.45,44.925 55.975,44.925 56.7,44.2 v1(56.7,43.875) ; TPJ606.1@97.404,47.202 v1@97.404,47.996
BC_VCOM_RXD_DIR: R850.2 U860.5 U900.M1 | length 2.6
  Top Layer w0.1: U900.M1@51.5,44 51.65,44 51.8,44.15 52.219,44.15 52.275,44.206 52.275,44.219 52.468,44.412 52.468,44.668 R850.2@52.8,45 U860.5@53.5,45
BC_VCOM_TXD: TPJ607.1 U861.3 U900.L1 | length 20.2
  Top Layer w0.1: U900.L1@51.5,43.5 51.518,43.518 52.169,43.518 52.329,43.357 52.662,43.357 53.144,42.875 v1(53.15,42.875) ; U861.3@64.55,40.45 64.55,40.575 64.758,40.782 65.213,40.782 65.443,41.012 65.443,41.818 v1(65.5,41.875)
  Bottom Layer w0.1: v1(53.15,42.875) 53.15,43 53.325,43.175 55.65,43.175 56.025,42.8 56.675,42.8 56.975,43.1 63.5,43.1 64.85,41.75 65.375,41.75 v1(65.5,41.875) 65.5,42.7 66.653,43.853 TPJ607.1@66.653,44.101
BC_VCOM_TXD_DIR: R851.2 U861.5 U900.N1 | length 15.8
  Top Layer w0.1: U900.N1@51.5,44.5 51.5,44.809 51.941,45.25 v1(52.25,45.25) ; v1(63.775,42.175) 63.825,42.175 R851.2@64.2,41.8 U861.5@64.2,41.15
  Signal Layer 4 w0.1: v1(52.25,45.25) 52.25,45.189 52.218,45.157 54.607,45.157 55.175,45.725 57.075,45.725 59.775,43.025 62.925,43.025 v1(63.775,42.175)
BOARD_ID_SCL: R907.2 U900.H13 U901.6 U950.4 | length 26.1
  Top Layer w0.1: v1(44.725,42.25) 45.25,42.25 U900.H13@45.5,42 ; U950.4@54.725,42.785 54.725,43.05 55.107,43.432 55.107,44.107 55.15,44.15 v1(55.2,44.15) ; U901.6@55.2,46.75 55.42,46.75 55.87,47.2 v1(55.95,47.2) 56.025,47.2 R907.2@56.475,46.75
  Signal Layer 3 w0.1: v1(44.725,42.25) 45.975,43.5 46.5,44.025 46.5,46.875 45.975,47.4 45.725,47.65 v1(45.725,48.25) ; v1(55.2,44.15) 55.15,44.15 55.057,44.243 55.057,46.307 v1(55.95,47.2)
  Signal Layer 4 w0.1: v1(45.725,48.25) 45.725,47.8 46.025,47.5 47.2,47.5 47.8,48.1 52.9,48.1 53.8,47.2 v1(55.95,47.2)
BOARD_ID_SDA: R908.2 U900.J12 U901.5 U950.2 | length 25.4
  Top Layer w0.1: v1(44.85,43.15) 45.25,42.75 45.75,42.75 U900.J12@46,42.5 ; U901.5@55.2,46.25 55.5,46.25 55.5,46.3 55.575,46.375 v1(55.925,46.375) 56.3,46.375 R908.2@56.475,46.2 ; U950.2@55.525,42.785 55.525,43.025 56.025,43.525 v1(56.025,43.925) ; v1@55.925,46.35 55.925,46.25 v1@55.975,46.2
  Signal Layer 3 w0.1: v1(44.85,43.15) 45.7,44 46.1,44.4 46.1,46.775 45.7,47.175 45.075,47.8 v1(45.075,48.25) ; v1(55.925,46.375) 56.3,46 56.3,44.3 56.025,44.025 v1(56.025,43.925)
  Bottom Layer w0.1: v1(45.075,48.25) 46.625,46.7 49.825,46.7 50.857,45.668 50.874,45.668 50.891,45.65 51.65,45.65 52.375,46.375 v1(55.925,46.375)
BOARD_ID_WP: R909.2 U900.F13 U901.7 | length 19.6
  Top Layer w0.1: v1(44.975,41.4) 45.1,41.4 U900.F13@45.5,41 ; v1(53.975,48.125) 54.35,48.125 54.675,47.8 54.675,47.5 54.925,47.25 U901.7@55.2,47.25 55.42,47.25 55.77,47.6 56.175,47.6 R909.2@56.475,47.3
  Signal Layer 3 w0.1: v1(44.975,41.4) 46.275,42.7 46.275,43 46.9,43.625 46.9,47.325 v1(46.275,47.95) v1@46.275,48
  Signal Layer 4 w0.1: v1@46.275,48 46.593,48.318 53.782,48.318 v1(53.975,48.125)
BOARD_VER0: R930.1 U900.M5 | length 9.5
  Top Layer w0.1: v1(47.55,42.375) 48,42.825 48,43.125 48.032,43.157 48.032,43.163 48.25,43.381 48.25,43.604 48.25,43.65 48.35,43.75 49.25,43.75 U900.M5@49.5,44 ; R930.1@49.8,46.5 50.3,47 v1(50.325,47)
  Signal Layer 3 w0.1: v1(47.55,42.375) 48.025,42.85 48.025,43.375 49.532,44.882 49.532,46.207 v1(50.325,47)
BOARD_VER1: R931.1 U900.M6 | length 2.9
  Top Layer w0.1: U900.M6@49,44 48.75,44.25 48.75,44.775 48.61,44.916 48.61,45.384 48.9,45.675 48.9,46.15 R931.1@49.25,46.5
BREAKOUT_BOT3: J101.3 R314.1 U1.9 | length 64.6
  Top Layer w0.1: v1(34.825,5.8) 34.875,5.75 R314.1@36,5.75 36,3.292 J101.3@36.03,3.262 ; J101.3@35.95,2.962 J101.3@36,3.012 ; v1(78.329,30.376) 78.329,30.421 78.325,30.425 78.35,30.425 78.35,30.925 79.825,32.4 81.726,32.4 82.326,31.8 U1.9@82.665,31.8
  Signal Layer 4 w0.1: v1(34.825,5.8) 34.825,8.225 46.725,20.125 67.375,20.125 77.626,30.376 v1(78.329,30.376)
BREAKOUT_BOT4: J101.4 P101.13 R315.1 U1.10 | length 96.7
  Top Layer w0.1: v1(37.3,5.7) 38.55,5.7 R315.1@38.6,5.75 38.6,3.292 J101.4@38.57,3.262 ; J101.4@38.55,2.962 J101.4@38.6,3.012 ; v1(79.079,30.376) 79.075,30.38 79.075,31.175 80.1,32.2 81.525,32.2 82.325,31.4 U1.10@82.665,31.4 ; v1(108.75,32.7) 108.76,32.71 P101.13@108.76,33.81
  Signal Layer 4 w0.1: v1(37.3,5.7) v1@37.325,5.7 ; v1(108.75,32.7) 108,33.45 96.025,33.45 95.275,32.7 92.3,32.7 89.9,30.3 79.155,30.3 v1(79.079,30.376) 78.652,29.95 77.55,29.95 67.45,19.85 47.325,19.85 36.825,9.35 36.825,6.2 v1@37.325,5.7 ; v1@37.325,5.7 37.413,5.613 37.5,5.7 v1@37.325,5.7
BREAKOUT_BOT5: J101.5 P101.14 R310.1 U1.16 | length 83.4
  Top Layer w0.1: J101.5@41.05,2.962 J101.5@41.1,3.012 ; J101.5@41.11,3.262 41.1,3.272 R310.1@41.1,5.75 v1(42.275,5.75) ; v1(84.55,29.05) 84.6,29.1 U1.16@84.6,29.865 ; v1(101.78,33.052) 101.78,33.07 101.775,33.075 101.8,33.1 102.875,33.1 103.585,33.81 P101.14@104.57,33.81
  Signal Layer 3 w0.1: v1(42.275,5.75) 42.275,13.825 v1(46.2,17.75) ; v1@101.748,33.052 v1(101.78,33.052)
  Signal Layer 4 w0.1: v1(46.2,17.75) 46.225,17.75 48,19.525 67.55,19.525 74.325,26.3 81.8,26.3 v1(84.55,29.05) 85.4,29.9 90.9,29.9 91.9,30.9 96.825,30.9 96.925,30.8 99.528,30.8 v1(101.78,33.052)
BREAKOUT_BOT6: J101.6 P101.12 R309.1 U1.17 | length 80.7
  Top Layer w0.1: J101.6@43.55,2.962 J101.6@43.6,3.012 ; J101.6@43.65,3.262 43.6,3.312 R309.1@43.6,5.75 44.25,6.4 v1(44.25,7.225) ; v1(84.55,28.4) 85,28.85 U1.17@85,29.865 ; v1(101.775,31.275) 101.78,31.27 P101.12@104.57,31.27
  Signal Layer 3 w0.1: v1(44.25,7.225) 44.25,14.425 v1(47.05,17.225)
  Signal Layer 4 w0.1: v1(47.05,17.225) 49.05,19.225 67.65,19.225 74.475,26.05 82.2,26.05 v1(84.55,28.4) 84.55,28.494 84.943,28.887 84.943,29.101 85.542,29.7 91.3,29.7 91.4,29.6 92.3,29.6 92.5,29.8 96.525,29.8 97.225,30.5 101,30.5 v1(101.775,31.275)
BREAKOUT_BOT7: J101.7 P101.11 R308.1 U1.18 | length 84.5
  Top Layer w0.1: J101.7@46.15,2.962 J101.7@46.2,3.012 ; J101.7@46.19,3.262 46.2,3.272 R308.1@46.2,5.75 46.275,5.675 v1(47.45,5.675) ; v1(85.325,28.525) 85.4,28.6 U1.18@85.4,29.865 ; P101.11@108.76,31.27 108.76,30.165 v1(108.775,30.15)
  Signal Layer 3 w0.1: v1(47.45,5.675) 47.45,13.525 47.6,13.675 v1(47.6,16.475)
  Signal Layer 4 w0.1: v1(47.6,16.475) 50,18.875 67.75,18.875 74.65,25.775 82.575,25.775 v1(85.325,28.525) 85.325,29.081 85.744,29.5 88.1,29.5 88.3,29.3 97,29.3 97.85,30.15 v1(108.775,30.15)
BREAKOUT_BOT8: J101.8 P101.7 R317.2 | length 75.5
  Top Layer w0.1: J101.8@48.65,3.062 J101.8@48.7,3.112 ; J101.8@48.73,3.262 48.7,3.292 R317.2@48.7,5.75 48.725,5.725 v1(49.925,5.725) ; v1(108.75,25.175) 108.76,25.185 P101.7@108.76,26.19
  Signal Layer 4 w0.1: v1(49.925,5.725) 50.75,4.9 71.95,4.9 72.725,4.125 91.1,4.125 109.275,22.3 109.275,24.65 v1(108.75,25.175)
BREAKOUT_BOT9: J101.9 R306.1 U1.20 | length 55.2
  Top Layer w0.1: J101.9@51.25,3.162 J101.9@51.3,3.212 ; R306.1@51.25,5.7 R306.1@51.275,5.725 ; J101.9@51.27,3.262 51.3,3.292 R306.1@51.3,5.725 ; v1(52.475,5.725) R306.1@51.3,5.725 ; v1(86.15,28.475) 86.218,28.543 86.218,29.847 U1.20@86.2,29.865 ; R306.1@51.275,5.725 R306.1@51.3,5.725 ; R306.1@51.275,5.725 R306.1@51.3,5.75 R306.1@51.3,5.725
  Signal Layer 3 w0.1: v1(52.475,5.725) 51.6,6.6 51.6,9.9 53.075,11.375 v1(53.075,16.475)
  Signal Layer 4 w0.1: v1(53.075,16.475) 54.85,18.25 68,18.25 75.025,25.275 83.15,25.275 86.15,28.275 v1(86.15,28.475)
BREAKOUT_BOT10: J101.10 R305.1 U1.21 | length 51.9
  Top Layer w0.1: J101.10@53.75,3.262 J101.10@53.8,3.312 ; J101.10@53.81,3.262 53.8,3.272 J101.10@53.8,3.312 ; v1(55.075,5.7) 53.85,5.7 R305.1@53.8,5.75 J101.10@53.8,3.312 ; U1.21@86.6,29.865 86.6,29.05 v1(86.625,29.025)
  Signal Layer 3 w0.1: v1(55.075,5.7) 56.1,6.725 v1(56.1,16.3)
  Signal Layer 4 w0.1: v1(56.1,16.3) 56.125,16.3 57.75,17.925 68.125,17.925 75.175,24.975 83.275,24.975 86.625,28.325 v1(86.625,29.025)
BREAKOUT_BOT11: J101.11 P101.5 R316.2 | length 63.8
  Top Layer w0.1: J101.11@56.35,3.262 56.4,3.312 R316.2@56.4,5.75 v1(57.55,5.75) ; v1(108.76,22.635) P101.5@108.76,23.65
  Signal Layer 4 w0.1: v1(57.55,5.75) 71.825,5.75 72.975,4.6 90.725,4.6 v1(108.76,22.635)
BREAKOUT_BOT12: J101.12
BREAKOUT_BOT13: C8.1 J101.13 Q800.6 SW1.1 SW1.2 TP400.1 U1.13 | length 94
  Top Layer w0.1: Q800.6@64.925,37.55 65.2,37.55 v1(65.4,37.35) ; v1(83,28.425) C8.1@83,28.9 83.4,29.3 U1.13@83.4,29.865 ; v1(97.75,33.05) 97.75,33.1 97.925,33.275 SW1.1@97.925,35.625 SW1.2@97.925,39.775
  Signal Layer 3 w0.1: J101.13@61.43,3.262 62.718,4.55 64.775,4.55 65.2,4.125 65.2,2.775 66.15,1.825 70.55,1.825 74.275,5.55 74.275,25.7 v1(75.375,26.8) 75.375,34 74.3,35.075 v1(74.3,37.2)
  Signal Layer 4 w0.1: v1(65.4,37.35) 65.8,37.35 66.45,36.7 68.812,36.7 69.112,37 74.1,37 v1(74.3,37.2) v1@74.3,37.175 ; v1(75.375,26.8) 77,28.425 v1(83,28.425) 83,29.05 84.05,30.1 90.1,30.1 92.2,32.2 97,32.2 97.725,32.925 97.725,33.075 v1(97.75,33.05)
  Bottom Layer w0.1: TP400.1@82.175,28.4 82.975,28.4 v1(83,28.425)
BREAKOUT_TOP3: J102.3
BREAKOUT_TOP4: J102.4
BREAKOUT_TOP5: J102.5
BREAKOUT_TOP6: J102.6
BREAKOUT_TOP7: J102.7
BREAKOUT_TOP8: J102.8 P101.15 R303.1 U1.35 | length 84
  Top Layer w0.1: J102.8@48.73,56.602 48.7,56.572 R303.1@48.7,54.15 49.85,54.15 v1(49.9,54.1) ; U1.35@88.535,34.6 92.375,34.6 92.55,34.775 v1(92.55,34.825) ; P101.15@108.76,36.35 108.76,35.465 v1(108.825,35.4)
  Signal Layer 3 w0.1: v1(91.725,47.45) 92.55,46.625 v1(92.55,34.825)
  Signal Layer 4 w0.1: v1(92.55,34.825) 93.575,35.85 108.375,35.85 v1(108.825,35.4)
  Bottom Layer w0.1: v1(49.9,54.1) 49.9,53.325 52.225,51 68.9,51 72.8,47.1 91.375,47.1 v1(91.725,47.45)
BREAKOUT_TOP9: J102.9 P101.16 R302.1 U1.34 | length 79.3
  Top Layer w0.1: J102.9@51.27,56.602 51.27,54.18 R302.1@51.3,54.15 51.95,54.15 v1(52.425,54.15) ; U1.34@88.535,34.2 88.875,34.2 89.075,34.4 92.325,34.4 v1(92.525,34.2) ; v1(101.775,35.375) 102.65,35.375 103.625,36.35 P101.16@104.57,36.35
  Signal Layer 3 w0.1: v1(92.525,34.2) 93,34.675 93,48.3 v1(92.85,48.45)
  Signal Layer 4 w0.1: v1(52.425,54.15) 52.425,53.175 54.325,51.275 68.65,51.275 72.325,47.6 86.75,47.6 87.25,48.1 92.5,48.1 v1(92.85,48.45) ; v1(92.525,34.2) 92.6,34.2 93.775,35.375 v1(101.775,35.375)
